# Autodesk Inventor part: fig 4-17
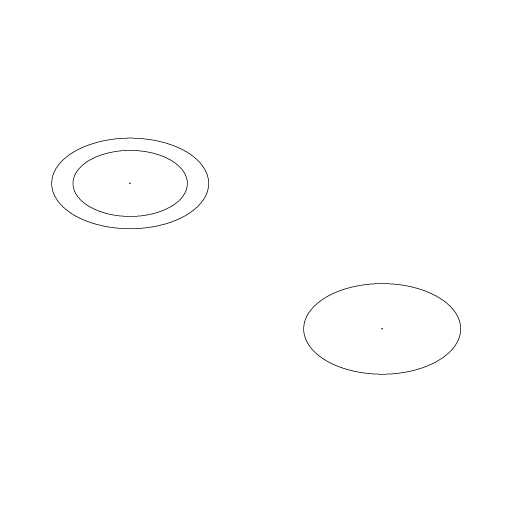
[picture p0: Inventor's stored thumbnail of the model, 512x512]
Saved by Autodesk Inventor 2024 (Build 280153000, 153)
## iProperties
Created: 2005-02
Part Number: fig 4-17
Document SubType Name: Modeling
Designer: CADCIM
Manufacturer: Standard
Standards Organization: Custom
Density: 1 g/cm^3
Material: Generic
Appearance: Default
Author: CADCIM
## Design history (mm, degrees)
sketch "Sketch1"
  geometry: C1 r 7.935 at (-23.563, 7.599); C2 r 7.935 at (12.452, 7.599); C3 r 5.782 at (-23.563, 7.599)
  constraints: 3 centre point, 1 coincident, 1 equal radius, 1 other
